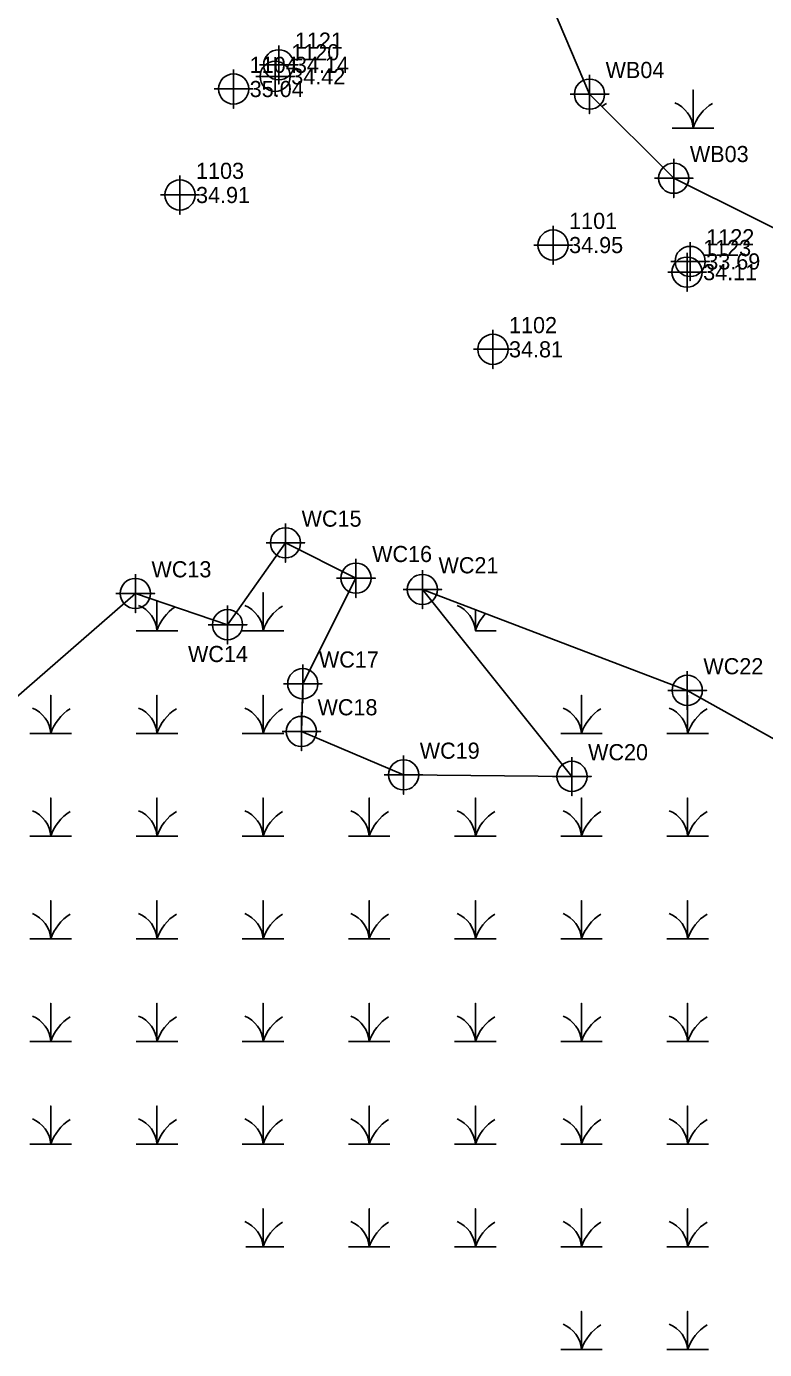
# Model space of a CAD drawing. Extents: x 2138832 to 2141061, y 149156 to 150675.
# Drawn here: x 2140400.8 to 2140515.2, y 149323 to 149528.1 of the extents above; entities that cross this region are included whole.
import ezdxf

# ---------------------------------------------------------------- set-up
doc = ezdxf.new("R2010")
doc.units = 0
for name, color, linetype in [('Exist Environmental Wetland Boundary', 7, 'Continuous'), ('Exist Environmental Wetland Boundary Cogo Number', 7, 'Continuous'), ('Exist Environmental Wetland Boundary Cogo Point CELL', 7, 'Continuous'), ('Exist Roads EOP Cogo Elevation', 7, 'Continuous'), ('Exist Roads EOP Cogo Number', 7, 'Continuous'), ('Exist Roads EOP Cogo Point CELL', 7, 'Continuous'), ('Exist Utilities Telephone UG FO SUE LOS C Cogo Elevation', 7, 'Continuous'), ('Exist Utilities Telephone UG FO SUE LOS C Cogo Number', 7, 'Continuous'), ('Exist Utilities Telephone UG FO SUE LOS C Cogo Point CELL', 7, 'Continuous')]:
    doc.layers.add(name, color=color, linetype=linetype)

msp = doc.modelspace()

# ---------------------------------------------------------------- linework, layer by layer
at = {"layer": 'Exist Environmental Wetland Boundary'}
for points in [[(2140220.74, 149663.51), (2140255.42, 149635.3), (2140277.39, 149631.77), (2140314.58, 149625.36), (2140349.86, 149614.36), (2140381.04, 149593.89), (2140416.32, 149561.58), (2140450.05, 149576.57), (2140474.9, 149577.61), (2140477.45, 149542.55), (2140488.03, 149517.58), (2140501.09, 149504.55), (2140539.61, 149485.41), (2140594.36, 149464.34)], [(2140253.29, 149429.4), (2140254.83, 149447.37), (2140264.97, 149452.77), (2140277.06, 149446.02), (2140283.85, 149449.07), (2140285.03, 149461.24), (2140314.82, 149458.43), (2140321.31, 149451.85), (2140338.41, 149446.15), (2140355.29, 149416.83), (2140380.43, 149428.6), (2140397.22, 149422.33), (2140417.64, 149440.18), (2140431.93, 149435.34), (2140440.91, 149448.03), (2140451.84, 149442.55), (2140443.59, 149426.19), (2140443.38, 149418.79), (2140459.22, 149412.06), (2140485.31, 149411.82), (2140462.13, 149440.8)], [(2140462.13, 149440.8), (2140503.18, 149425.15), (2140518.52, 149416.56), (2140523.47, 149412.6)]]:
    msp.add_lwpolyline(points, dxfattribs=at)
at = {"layer": 'Exist Environmental Wetland Boundary Cogo Point CELL'}
for points in [[(2140488.03, 149520.58), (2140488.03, 149514.58), (2140488.03, 149517.58), (2140491.03, 149517.58), (2140485.03, 149517.58)], [(2140500.86, 149512.32), (2140504.09, 149512.32), (2140504.09, 149518.24), (2140504.09, 149512.32), (2140507.31, 149512.32)], [(2140501.09, 149507.55), (2140501.09, 149501.55), (2140501.09, 149504.55), (2140504.09, 149504.55), (2140498.09, 149504.55)], [(2140440.91, 149451.03), (2140440.91, 149445.03), (2140440.91, 149448.03), (2140443.91, 149448.03), (2140437.91, 149448.03)], [(2140451.84, 149445.55), (2140451.84, 149439.55), (2140451.84, 149442.55), (2140454.84, 149442.55), (2140448.84, 149442.55)], [(2140417.64, 149443.18), (2140417.64, 149437.18), (2140417.64, 149440.18), (2140420.64, 149440.18), (2140414.64, 149440.18)], [(2140462.13, 149443.8), (2140462.13, 149437.8), (2140462.13, 149440.8), (2140465.13, 149440.8), (2140459.13, 149440.8)], [(2140417.76, 149434.4), (2140420.99, 149434.4), (2140420.99, 149439.04)], [(2140420.99, 149439.04), (2140420.99, 149434.4), (2140424.21, 149434.4)], [(2140434.21, 149434.4), (2140437.44, 149434.4), (2140437.44, 149440.32), (2140437.44, 149434.4), (2140440.66, 149434.4)], [(2140431.93, 149438.34), (2140431.93, 149432.34), (2140431.93, 149435.34), (2140434.93, 149435.34), (2140428.93, 149435.34)], [(2140470.34, 149437.67), (2140470.34, 149434.4), (2140473.57, 149434.4)], [(2140443.59, 149429.19), (2140443.59, 149423.19), (2140443.59, 149426.19), (2140446.59, 149426.19), (2140440.59, 149426.19)], [(2140503.18, 149428.15), (2140503.18, 149422.15), (2140503.18, 149425.15), (2140506.18, 149425.15), (2140500.18, 149425.15)], [(2140401.31, 149418.48), (2140404.54, 149418.48), (2140404.54, 149424.4), (2140404.54, 149418.48), (2140407.76, 149418.48)], [(2140417.76, 149418.48), (2140420.99, 149418.48), (2140420.99, 149424.4), (2140420.99, 149418.48), (2140424.21, 149418.48)], [(2140434.21, 149418.48), (2140437.44, 149418.48), (2140437.44, 149424.4), (2140437.44, 149418.48), (2140440.66, 149418.48)], [(2140483.57, 149418.48), (2140486.79, 149418.48), (2140486.79, 149424.4), (2140486.79, 149418.48), (2140490.02, 149418.48)], [(2140500.02, 149418.48), (2140503.24, 149418.48), (2140503.24, 149424.4), (2140503.24, 149418.48), (2140506.47, 149418.48)], [(2140443.38, 149421.79), (2140443.38, 149415.79), (2140443.38, 149418.79), (2140446.38, 149418.79), (2140440.38, 149418.79)], [(2140459.22, 149415.06), (2140459.22, 149409.06), (2140459.22, 149412.06), (2140462.22, 149412.06), (2140456.22, 149412.06)], [(2140485.31, 149414.82), (2140485.31, 149408.82), (2140485.31, 149411.82), (2140488.31, 149411.82), (2140482.31, 149411.82)], [(2140401.31, 149402.56), (2140404.54, 149402.56), (2140404.54, 149408.48), (2140404.54, 149402.56), (2140407.76, 149402.56)], [(2140417.76, 149402.56), (2140420.99, 149402.56), (2140420.99, 149408.48), (2140420.99, 149402.56), (2140424.21, 149402.56)], [(2140434.21, 149402.56), (2140437.44, 149402.56), (2140437.44, 149408.48), (2140437.44, 149402.56), (2140440.66, 149402.56)], [(2140450.66, 149402.56), (2140453.89, 149402.56), (2140453.89, 149408.48), (2140453.89, 149402.56), (2140457.11, 149402.56)], [(2140467.11, 149402.56), (2140470.34, 149402.56), (2140470.34, 149408.48), (2140470.34, 149402.56), (2140473.57, 149402.56)], [(2140483.57, 149402.56), (2140486.79, 149402.56), (2140486.79, 149408.48), (2140486.79, 149402.56), (2140490.02, 149402.56)], [(2140500.02, 149402.56), (2140503.24, 149402.56), (2140503.24, 149408.48), (2140503.24, 149402.56), (2140506.47, 149402.56)], [(2140401.31, 149386.65), (2140404.54, 149386.65), (2140404.54, 149392.56), (2140404.54, 149386.65), (2140407.76, 149386.65)], [(2140417.76, 149386.65), (2140420.99, 149386.65), (2140420.99, 149392.56), (2140420.99, 149386.65), (2140424.21, 149386.65)], [(2140434.21, 149386.65), (2140437.44, 149386.65), (2140437.44, 149392.56), (2140437.44, 149386.65), (2140440.66, 149386.65)], [(2140450.66, 149386.65), (2140453.89, 149386.65), (2140453.89, 149392.56), (2140453.89, 149386.65), (2140457.11, 149386.65)], [(2140467.11, 149386.65), (2140470.34, 149386.65), (2140470.34, 149392.56), (2140470.34, 149386.65), (2140473.57, 149386.65)], [(2140483.57, 149386.65), (2140486.79, 149386.65), (2140486.79, 149392.56), (2140486.79, 149386.65), (2140490.02, 149386.65)], [(2140500.02, 149386.65), (2140503.24, 149386.65), (2140503.24, 149392.56), (2140503.24, 149386.65), (2140506.47, 149386.65)], [(2140401.31, 149370.73), (2140404.54, 149370.73), (2140404.54, 149376.65), (2140404.54, 149370.73), (2140407.76, 149370.73)], [(2140417.76, 149370.73), (2140420.99, 149370.73), (2140420.99, 149376.65), (2140420.99, 149370.73), (2140424.21, 149370.73)], [(2140434.21, 149370.73), (2140437.44, 149370.73), (2140437.44, 149376.65), (2140437.44, 149370.73), (2140440.66, 149370.73)], [(2140450.66, 149370.73), (2140453.89, 149370.73), (2140453.89, 149376.65), (2140453.89, 149370.73), (2140457.11, 149370.73)], [(2140467.11, 149370.73), (2140470.34, 149370.73), (2140470.34, 149376.65), (2140470.34, 149370.73), (2140473.57, 149370.73)], [(2140483.57, 149370.73), (2140486.79, 149370.73), (2140486.79, 149376.65), (2140486.79, 149370.73), (2140490.02, 149370.73)], [(2140500.02, 149370.73), (2140503.24, 149370.73), (2140503.24, 149376.65), (2140503.24, 149370.73), (2140506.47, 149370.73)], [(2140401.31, 149354.81), (2140404.54, 149354.81), (2140404.54, 149360.73), (2140404.54, 149354.81), (2140407.76, 149354.81)], [(2140417.76, 149354.81), (2140420.99, 149354.81), (2140420.99, 149360.73), (2140420.99, 149354.81), (2140424.21, 149354.81)], [(2140434.21, 149354.81), (2140437.44, 149354.81), (2140437.44, 149360.73), (2140437.44, 149354.81), (2140440.66, 149354.81)], [(2140450.66, 149354.81), (2140453.89, 149354.81), (2140453.89, 149360.73), (2140453.89, 149354.81), (2140457.11, 149354.81)], [(2140467.11, 149354.81), (2140470.34, 149354.81), (2140470.34, 149360.73), (2140470.34, 149354.81), (2140473.57, 149354.81)], [(2140483.57, 149354.81), (2140486.79, 149354.81), (2140486.79, 149360.73), (2140486.79, 149354.81), (2140490.02, 149354.81)], [(2140500.02, 149354.81), (2140503.24, 149354.81), (2140503.24, 149360.73), (2140503.24, 149354.81), (2140506.47, 149354.81)], [(2140434.78, 149338.89), (2140437.44, 149338.89), (2140437.44, 149344.81), (2140437.44, 149338.89), (2140440.66, 149338.89)], [(2140450.66, 149338.89), (2140453.89, 149338.89), (2140453.89, 149344.81), (2140453.89, 149338.89), (2140457.11, 149338.89)], [(2140467.11, 149338.89), (2140470.34, 149338.89), (2140470.34, 149344.81), (2140470.34, 149338.89), (2140473.57, 149338.89)], [(2140483.57, 149338.89), (2140486.79, 149338.89), (2140486.79, 149344.81), (2140486.79, 149338.89), (2140490.02, 149338.89)], [(2140500.02, 149338.89), (2140503.24, 149338.89), (2140503.24, 149344.81), (2140503.24, 149338.89), (2140506.47, 149338.89)], [(2140483.57, 149322.98), (2140486.79, 149322.98), (2140486.79, 149328.89), (2140486.79, 149322.98), (2140490.02, 149322.98)], [(2140500.02, 149322.98), (2140503.24, 149322.98), (2140503.24, 149328.89), (2140503.24, 149322.98), (2140506.47, 149322.98)]]:
    msp.add_lwpolyline(points, dxfattribs=at)
for centre in [(2140488.03, 149517.58), (2140501.09, 149504.55), (2140440.91, 149448.03), (2140451.84, 149442.55), (2140462.13, 149440.8), (2140417.64, 149440.18), (2140431.93, 149435.34), (2140443.59, 149426.19), (2140503.18, 149425.15), (2140443.38, 149418.79), (2140459.22, 149412.06), (2140485.31, 149411.82)]:
    msp.add_circle(centre, 2.34, dxfattribs=at)
for centre, radius, start, end in [((2140494.48, 149510.05), 7.21, 122.1274, 128.8575), ((2140499.49, 149511.99), 4.61, 4.1403, 67.535), ((2140510.93, 149510.05), 7.21, 122.1274, 161.6222), ((2140416.39, 149434.07), 4.61, 4.1403, 67.535), ((2140427.83, 149432.13), 7.21, 124.1034, 161.6222), ((2140432.84, 149434.07), 4.61, 4.1403, 67.535), ((2140444.28, 149432.13), 7.21, 122.1274, 161.6222), ((2140465.74, 149434.07), 4.61, 4.1403, 67.535), ((2140477.18, 149432.13), 7.21, 136.7735, 161.6222), ((2140399.94, 149418.15), 4.61, 4.1403, 67.535), ((2140411.38, 149416.21), 7.21, 122.1274, 161.6222), ((2140416.39, 149418.15), 4.61, 4.1403, 67.535), ((2140427.83, 149416.21), 7.21, 122.1274, 161.6222), ((2140432.84, 149418.15), 4.61, 4.1403, 67.535), ((2140444.28, 149416.21), 7.21, 122.1274, 161.6222), ((2140482.19, 149418.15), 4.61, 4.1403, 67.535), ((2140493.63, 149416.21), 7.21, 122.1274, 161.6222), ((2140498.64, 149418.15), 4.61, 4.1403, 67.535), ((2140510.08, 149416.21), 7.21, 122.1274, 161.6222), ((2140399.94, 149402.23), 4.61, 4.1403, 67.535), ((2140411.38, 149400.29), 7.21, 122.1274, 161.6222), ((2140416.39, 149402.23), 4.61, 4.1403, 67.535), ((2140427.83, 149400.29), 7.21, 122.1274, 161.6222), ((2140432.84, 149402.23), 4.61, 4.1403, 67.535), ((2140444.28, 149400.29), 7.21, 122.1274, 161.6222), ((2140449.29, 149402.23), 4.61, 4.1403, 67.535), ((2140460.73, 149400.29), 7.21, 122.1274, 161.6222), ((2140465.74, 149402.23), 4.61, 4.1403, 67.535), ((2140477.18, 149400.29), 7.21, 122.1274, 161.6222), ((2140482.19, 149402.23), 4.61, 4.1403, 67.535), ((2140493.63, 149400.29), 7.21, 122.1274, 161.6222), ((2140498.64, 149402.23), 4.61, 4.1403, 67.535), ((2140510.08, 149400.29), 7.21, 122.1274, 161.6222), ((2140399.94, 149386.31), 4.61, 4.1403, 67.535), ((2140411.38, 149384.37), 7.21, 122.1274, 161.6222), ((2140416.39, 149386.31), 4.61, 4.1403, 67.535), ((2140427.83, 149384.37), 7.21, 122.1274, 161.6222), ((2140432.84, 149386.31), 4.61, 4.1403, 67.535), ((2140444.28, 149384.37), 7.21, 122.1274, 161.6222), ((2140449.29, 149386.31), 4.61, 4.1403, 67.535), ((2140460.73, 149384.37), 7.21, 122.1274, 161.6222), ((2140465.74, 149386.31), 4.61, 4.1403, 67.535), ((2140477.18, 149384.37), 7.21, 122.1274, 161.6222), ((2140482.19, 149386.31), 4.61, 4.1403, 67.535), ((2140493.63, 149384.37), 7.21, 122.1274, 161.6222), ((2140498.64, 149386.31), 4.61, 4.1403, 67.535), ((2140510.08, 149384.37), 7.21, 122.1274, 161.6222), ((2140399.94, 149370.4), 4.61, 4.1403, 67.535), ((2140411.38, 149368.46), 7.21, 122.1274, 161.6222), ((2140416.39, 149370.4), 4.61, 4.1403, 67.535), ((2140427.83, 149368.46), 7.21, 122.1274, 161.6222), ((2140432.84, 149370.4), 4.61, 4.1403, 67.535), ((2140444.28, 149368.46), 7.21, 122.1274, 161.6222), ((2140449.29, 149370.4), 4.61, 4.1403, 67.535), ((2140460.73, 149368.46), 7.21, 122.1274, 161.6222), ((2140465.74, 149370.4), 4.61, 4.1403, 67.535), ((2140477.18, 149368.46), 7.21, 122.1274, 161.6222), ((2140482.19, 149370.4), 4.61, 4.1403, 67.535), ((2140493.63, 149368.46), 7.21, 122.1274, 161.6222), ((2140498.64, 149370.4), 4.61, 4.1403, 67.535), ((2140510.08, 149368.46), 7.21, 122.1274, 161.6222), ((2140399.94, 149354.48), 4.61, 4.1403, 67.535), ((2140411.38, 149352.54), 7.21, 122.1274, 161.6222), ((2140416.39, 149354.48), 4.61, 4.1403, 67.535), ((2140427.83, 149352.54), 7.21, 122.1274, 161.6222), ((2140432.84, 149354.48), 4.61, 4.1403, 67.535), ((2140444.28, 149352.54), 7.21, 122.1274, 161.6222), ((2140449.29, 149354.48), 4.61, 4.1403, 67.535), ((2140460.73, 149352.54), 7.21, 122.1274, 161.6222), ((2140465.74, 149354.48), 4.61, 4.1403, 67.535), ((2140477.18, 149352.54), 7.21, 122.1274, 161.6222), ((2140482.19, 149354.48), 4.61, 4.1403, 67.535), ((2140493.63, 149352.54), 7.21, 122.1274, 161.6222), ((2140498.64, 149354.48), 4.61, 4.1403, 67.535), ((2140510.08, 149352.54), 7.21, 122.1274, 161.6222), ((2140432.84, 149338.56), 4.61, 4.1403, 67.535), ((2140444.28, 149336.62), 7.21, 122.1274, 161.6222), ((2140449.29, 149338.56), 4.61, 4.1403, 67.535), ((2140460.73, 149336.62), 7.21, 122.1274, 161.6222), ((2140465.74, 149338.56), 4.61, 4.1403, 67.535), ((2140477.18, 149336.62), 7.21, 122.1274, 161.6222), ((2140482.19, 149338.56), 4.61, 4.1403, 67.535), ((2140493.63, 149336.62), 7.21, 122.1274, 161.6222), ((2140498.64, 149338.56), 4.61, 4.1403, 67.535), ((2140510.08, 149336.62), 7.21, 122.1274, 161.6222), ((2140482.19, 149322.64), 4.61, 4.1403, 67.535), ((2140493.63, 149320.7), 7.21, 122.1274, 161.6222), ((2140498.64, 149322.64), 4.61, 4.1403, 67.535), ((2140510.08, 149320.7), 7.21, 122.1274, 161.6222)]:
    msp.add_arc(centre, radius, start, end, dxfattribs=at)
at = {"layer": 'Exist Roads EOP Cogo Point CELL'}
for points in [[(2140432.87, 149521.38), (2140432.87, 149515.38), (2140432.87, 149518.38), (2140435.87, 149518.38), (2140429.87, 149518.38)], [(2140424.55, 149504.95), (2140424.55, 149498.95), (2140424.55, 149501.95), (2140427.55, 149501.95), (2140421.55, 149501.95)], [(2140482.38, 149497.19), (2140482.38, 149491.19), (2140482.38, 149494.19), (2140485.38, 149494.19), (2140479.38, 149494.19)], [(2140473.06, 149481.03), (2140473.06, 149475.03), (2140473.06, 149478.03), (2140476.06, 149478.03), (2140470.06, 149478.03)]]:
    msp.add_lwpolyline(points, dxfattribs=at)
for centre in [(2140432.87, 149518.38), (2140424.55, 149501.95), (2140482.38, 149494.19), (2140473.06, 149478.03)]:
    msp.add_circle(centre, 2.34, dxfattribs=at)
at = {"layer": 'Exist Utilities Telephone UG FO SUE LOS C Cogo Point CELL'}
for points in [[(2140439.87, 149525.13), (2140439.87, 149519.13), (2140439.87, 149522.13), (2140442.87, 149522.13), (2140436.87, 149522.13)], [(2140439.31, 149523.33), (2140439.31, 149517.33), (2140439.31, 149520.33), (2140442.31, 149520.33), (2140436.31, 149520.33)], [(2140503.63, 149494.65), (2140503.63, 149488.65), (2140503.63, 149491.65), (2140506.63, 149491.65), (2140500.63, 149491.65)], [(2140503.15, 149492.99), (2140503.15, 149486.99), (2140503.15, 149489.99), (2140506.15, 149489.99), (2140500.15, 149489.99)]]:
    msp.add_lwpolyline(points, dxfattribs=at)
for centre in [(2140439.31, 149520.33), (2140439.87, 149522.13), (2140503.63, 149491.65), (2140503.15, 149489.99)]:
    msp.add_circle(centre, 2.34, dxfattribs=at)

# ---------------------------------------------------------------- texts
at = {"layer": 'Exist Environmental Wetland Boundary Cogo Number'}
for s, p in [('WB04', (2140490.53, 149520.08)), ('WB03', (2140503.59, 149507.05)), ('WC15', (2140443.41, 149450.53)), ('WC16', (2140454.34, 149445.05)), ('WC13', (2140420.14, 149442.68)), ('WC21', (2140464.63, 149443.3)), ('WC14', (2140425.8, 149429.55)), ('WC17', (2140446.09, 149428.69)), ('WC22', (2140505.68, 149427.65)), ('WC18', (2140445.88, 149421.29)), ('WC19', (2140461.72, 149414.56)), ('WC20', (2140487.81, 149414.32))]:
    msp.add_text(s, height=2.5, dxfattribs=at).set_placement(p)
at = {"layer": 'Exist Roads EOP Cogo Elevation'}
for s, p in [('35.04', (2140435.37, 149517.13)), ('34.91', (2140427.05, 149500.7)), ('34.95', (2140484.88, 149492.94)), ('34.81', (2140475.56, 149476.78))]:
    msp.add_text(s, height=2.5, dxfattribs=at).set_placement(p)
at = {"layer": 'Exist Roads EOP Cogo Number'}
for s, p in [('1104', (2140435.37, 149520.88)), ('1103', (2140427.05, 149504.45)), ('1101', (2140484.88, 149496.69)), ('1102', (2140475.56, 149480.53))]:
    msp.add_text(s, height=2.5, dxfattribs=at).set_placement(p)
at = {"layer": 'Exist Utilities Telephone UG FO SUE LOS C Cogo Elevation'}
for s, p in [('34.14', (2140442.37, 149520.88)), ('34.42', (2140441.81, 149519.08)), ('33.69', (2140506.13, 149490.4)), ('34.11', (2140505.65, 149488.74))]:
    msp.add_text(s, height=2.5, dxfattribs=at).set_placement(p)
at = {"layer": 'Exist Utilities Telephone UG FO SUE LOS C Cogo Number'}
for s, p in [('1121', (2140442.37, 149524.63)), ('1120', (2140441.81, 149522.83)), ('1122', (2140506.13, 149494.15)), ('1123', (2140505.65, 149492.49))]:
    msp.add_text(s, height=2.5, dxfattribs=at).set_placement(p)

doc.saveas('drawing.dxf')
